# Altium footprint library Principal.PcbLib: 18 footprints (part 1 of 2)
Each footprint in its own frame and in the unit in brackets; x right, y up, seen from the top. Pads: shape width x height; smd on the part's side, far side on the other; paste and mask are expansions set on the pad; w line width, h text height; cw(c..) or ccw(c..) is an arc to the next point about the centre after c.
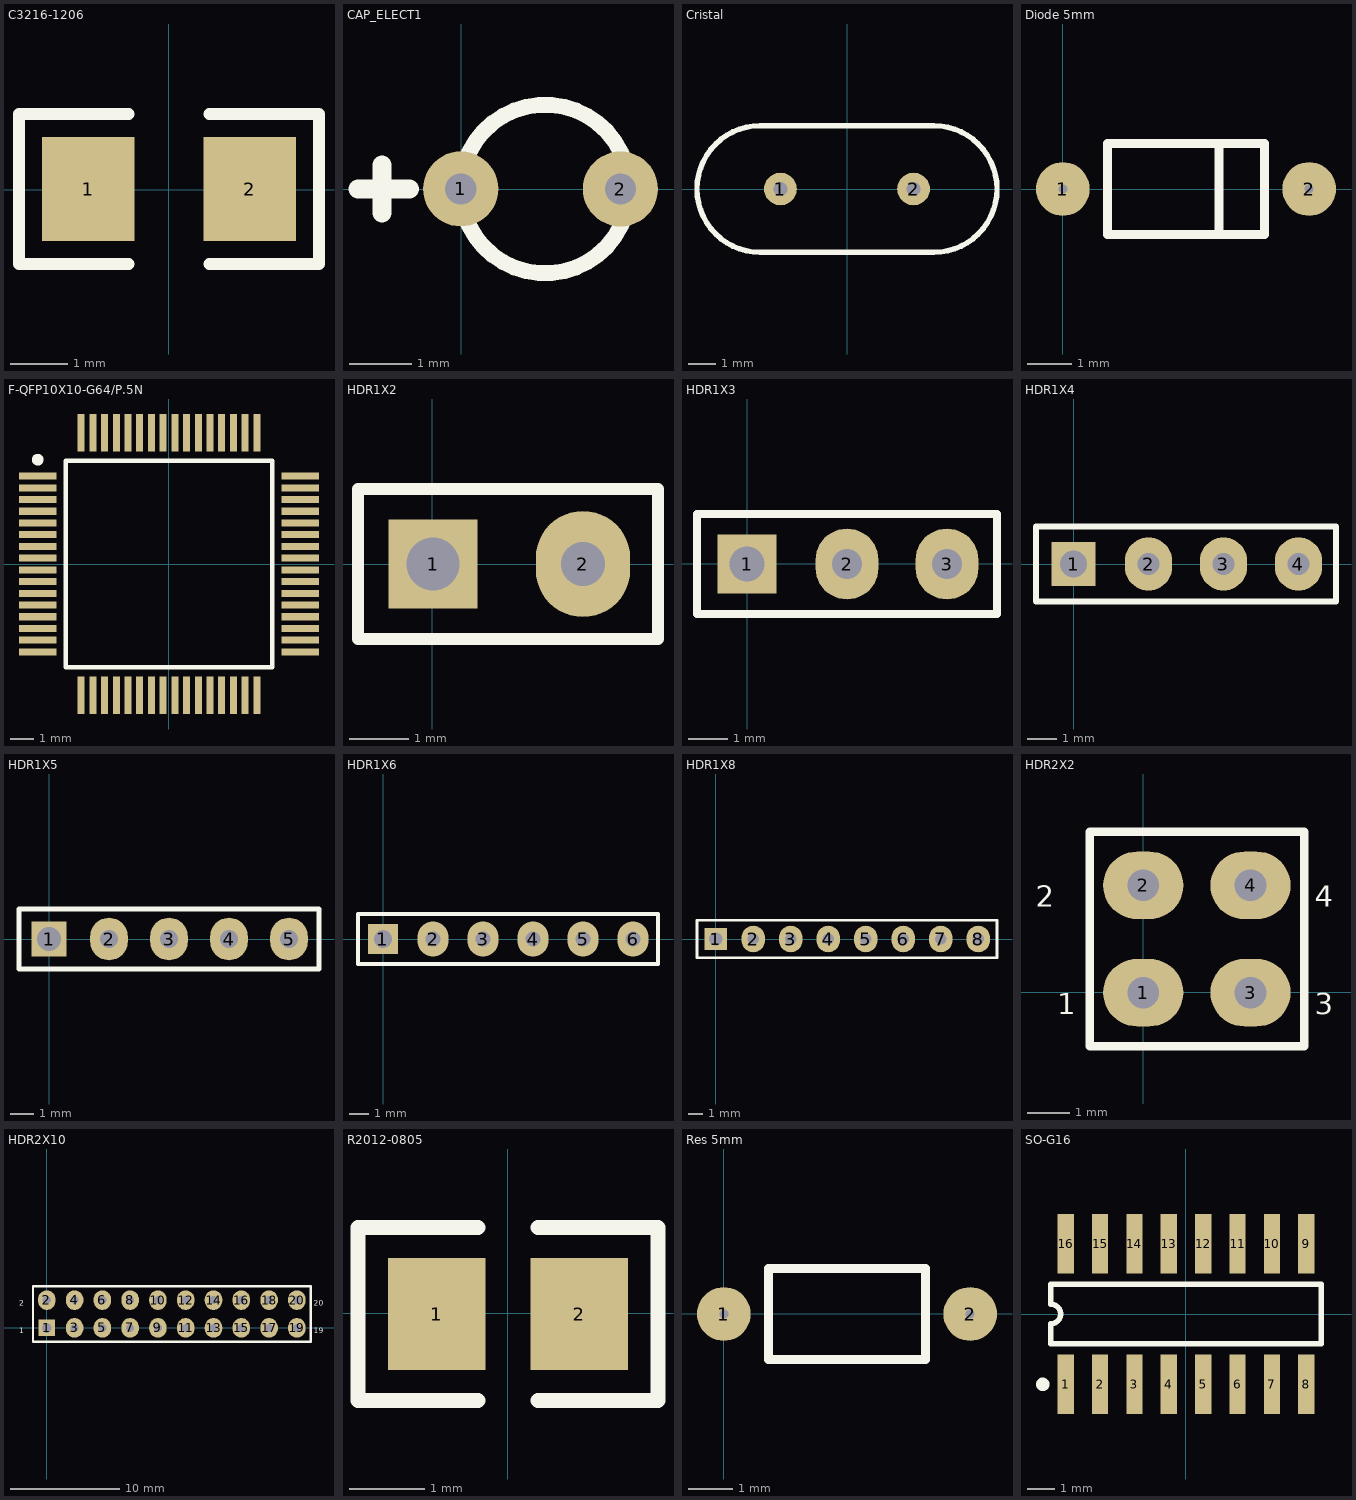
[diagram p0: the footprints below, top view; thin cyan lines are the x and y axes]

## C3216-1206 [mm]
pads (2):
  rect 1.6x1.8 smd: 1(-1.394,0.011) 2(1.406,0.011)
Top Overlay:
  lines w0.2: -0.694,-1.289 -2.594,-1.289 -2.594,1.311 -0.694,1.311 ; 0.706,-1.289 2.606,-1.289 2.606,1.311 0.706,1.311

## CAP_ELECT1 [mm]
pads (2):
  round 1.2 hole 0.5: 1(-0.01,0) 2(2.54,0)
Top Overlay:
  circle w0.254: c1.337,0 r1.347
  lines w0.305: -1.651,0 -0.826,0 ; -1.27,-0.381 -1.27,0.381

## Cristal [mm]
pads (2):
  round 1.2 hole 0.5: 1(-2.447,0.001) 2(2.433,0.001)
Top Overlay:
  lines w0.2: -3.182,-2.324 cw(c-3.182,0.001) -3.182,2.326 3.168,2.326 cw(c3.168,0.001) 3.168,-2.324 -3.182,-2.324

## Diode 5mm [mm]
pads (2):
  round 1.2 hole 0.2: 1(0.004,0.008) 2(5.504,0.008)
Top Overlay:
  lines w0.2: 1.004,-1.008 1.004,1.024 ; 1.02,-1.008 4.504,-1.008 4.504,1.024 1.02,1.024 ; 3.488,-1.008 3.488,1.024

## F-QFP10X10-G64/P.5N [mm]
pads (64):
  rect 1.6x0.3 smd: 1(-5.589,3.756) 2(-5.589,3.256) 3(-5.589,2.756) 4(-5.589,2.256) 5(-5.589,1.756) 6(-5.589,1.256) 7(-5.589,0.756) 8(-5.589,0.256) 9(-5.589,-0.244) 10(-5.589,-0.744) 11(-5.589,-1.244) 12(-5.589,-1.744) 13(-5.589,-2.244) 14(-5.589,-2.744) 15(-5.589,-3.244) 16(-5.589,-3.744) 33(5.611,-3.744) 34(5.611,-3.244) 35(5.611,-2.744) 36(5.611,-2.244) 37(5.611,-1.744) 38(5.611,-1.244) 39(5.611,-0.744) 40(5.611,-0.244) 41(5.611,0.256) 42(5.611,0.756) 43(5.611,1.256) 44(5.611,1.756) 45(5.611,2.256) 46(5.611,2.756) 47(5.611,3.256) 48(5.611,3.756)
  rect 0.3x1.6 smd: 17(-3.739,-5.594) 18(-3.239,-5.594) 19(-2.739,-5.594) 20(-2.239,-5.594) 21(-1.739,-5.594) 22(-1.239,-5.594) 23(-0.739,-5.594) 24(-0.239,-5.594) 25(0.261,-5.594) 26(0.761,-5.594) 27(1.261,-5.594) 28(1.761,-5.594) 29(2.261,-5.594) 30(2.761,-5.594) 31(3.261,-5.594) 32(3.761,-5.594) 49(3.761,5.606) 50(3.261,5.606) 51(2.761,5.606) 52(2.261,5.606) 53(1.761,5.606) 54(1.261,5.606) 55(0.761,5.606) 56(0.261,5.606) 57(-0.239,5.606) 58(-0.739,5.606) 59(-1.239,5.606) 60(-1.739,5.606) 61(-2.239,5.606) 62(-2.739,5.606) 63(-3.239,5.606) 64(-3.739,5.606)
Top Overlay:
  circle w0.25: c-5.589,4.456 r0.125
  lines w0.2: -4.389,-4.394 -4.389,4.406 4.411,4.406 4.411,-4.394 -4.389,-4.394

## HDR1X2 [mm]
pads (2):
  rect 1.5x1.5 hole 0.9: 1(0.009,0.007)
  oval 1.6x1.8 hole 0.75: 2(2.549,0.007)
Top Overlay:
  lines w0.2: -1.261,-1.263 -1.261,1.277 3.819,1.277 3.819,-1.263 -1.261,-1.263

## HDR1X3 [mm]
pads (3):
  rect 1.5x1.5 hole 0.9: 1(-0.006,-0.006)
  oval 1.6x1.8 hole 0.75: 2(2.534,-0.006) 3(5.074,-0.006)
Top Overlay:
  lines w0.2: -1.276,-1.276 6.344,-1.276 6.344,1.264 -1.276,1.264 -1.276,-1.276

## HDR1X4 [mm]
pads (4):
  rect 1.5x1.5 hole 0.9: 1(-0.009,0.009)
  oval 1.6x1.8 hole 0.75: 2(2.531,0.009) 3(5.071,0.009) 4(7.611,0.009)
Top Overlay:
  lines w0.2: -1.279,-1.261 -1.279,1.279 8.881,1.279 8.881,-1.261 -1.279,-1.261

## HDR1X5 [mm]
pads (5):
  rect 1.5x1.5 hole 1: 1(-0.009,0.009)
  oval 1.6x1.8 hole 0.75: 2(2.531,0.009) 3(5.071,0.009) 4(7.611,0.009) 5(10.151,0.009)
Top Overlay:
  lines w0.2: -1.279,-1.261 -1.279,1.279 11.421,1.279 11.421,-1.261 -1.279,-1.261

## HDR1X6 [mm]
pads (6):
  rect 1.5x1.5 hole 0.9: 1(-0.004,0.008)
  oval 1.6x1.8 hole 0.75: 2(2.536,0.008) 3(5.076,0.008) 4(7.616,0.008) 5(10.156,0.008) 6(12.696,0.008)
Top Overlay:
  lines w0.2: -1.274,-1.262 13.966,-1.262 13.966,1.278 -1.274,1.278 -1.274,-1.262

## HDR1X8 [mm]
pads (8):
  rect 1.5x1.5 hole 0.9: 1(-0.009,0.009)
  oval 1.6x1.8 hole 0.75: 2(2.531,0.009) 3(5.071,0.009) 4(7.611,0.009) 5(10.151,0.009) 6(12.691,0.009) 7(15.231,0.009) 8(17.771,0.009)
Top Overlay:
  lines w0.2: -1.279,-1.261 -1.279,1.279 19.041,1.279 19.041,-1.261 -1.279,-1.261

## HDR2X2 [mm]
pads (4):
  oval 1.9x1.6 hole 0.75: 1(-0.005,-0.012) 2(-0.005,2.528) 3(2.535,-0.012) 4(2.535,2.528)
Top Overlay:
  lines w0.2: -1.275,-1.282 -1.275,3.798 3.805,3.798 3.805,-1.282 -1.275,-1.282
  text "1" at -2.037,-0.52 h0.5
  text "2" at -2.545,2.02 h0.5
  text "4" at 4.059,2.02 h0.5
  text "3" at 4.059,-0.52 h0.5

## HDR2X10 [mm]
pads (20):
  rect 1.5x1.5 hole 0.9: 1(0.002,-0.003)
  oval 1.6x1.8 hole 0.75: 2(0.002,2.537) 3(2.542,-0.003) 4(2.542,2.537) 5(5.082,-0.003) 6(5.082,2.537) 7(7.622,-0.003) 8(7.622,2.537) 9(10.162,-0.003) 10(10.162,2.537) 11(12.702,-0.003) 12(12.702,2.537) 13(15.242,-0.003) 14(15.242,2.537) 15(17.782,-0.003) 16(17.782,2.537) 17(20.322,-0.003) 18(20.322,2.537) 19(22.862,-0.003) 20(22.862,2.537)
Top Overlay:
  lines w0.2: -1.268,-1.273 0.637,-1.273 24.132,-1.273 24.132,3.807 0.637,3.807 -1.268,3.807 -1.268,-1.273
  text "20" at 24.386,2.029 h0.5
  text "19" at 24.386,-0.511 h0.5
  text "1" at -2.538,-0.511 h0.5
  text "2" at -2.538,2.029 h0.5

## R2012-0805 [mm]
pads (2):
  rect 1.3x1.5 smd: 1(-0.95,-0.01) 2(0.95,-0.01)
Top Overlay:
  lines w0.2: -0.4,-1.16 -2,-1.16 -2,1.14 -0.4,1.14 ; 0.4,-1.16 2,-1.16 2,1.14 0.4,1.14

## Res 5mm [mm]
pads (2):
  round 1.2 hole 0.2: 1(-0.002,-0.004) 2(5.498,-0.004)
Top Overlay:
  lines w0.2: 0.998,-1.02 0.998,1.012 ; 1.014,-1.02 4.498,-1.02 4.498,1.012 1.014,1.012

## SO-G16 [mm]
pads (16):
  rect 0.6x2.2 smd: 1(-4.434,-2.589) 2(-3.164,-2.589) 3(-1.894,-2.589) 4(-0.624,-2.589) 5(0.646,-2.589) 6(1.916,-2.589) 7(3.186,-2.589) 8(4.456,-2.589) 9(4.456,2.611) 10(3.186,2.611) 11(1.916,2.611) 12(0.646,2.611) 13(-0.624,2.611) 14(-1.894,2.611) 15(-3.164,2.611) 16(-4.434,2.611)
Top Overlay:
  circle w0.25: c-5.284,-2.589 r0.125
  lines w0.2: -4.989,-1.089 -4.989,-0.356 ccw(c-4.989,0.011) -4.989,0.377 -4.989,1.111 5.011,1.111 5.011,-1.089 -4.989,-1.089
